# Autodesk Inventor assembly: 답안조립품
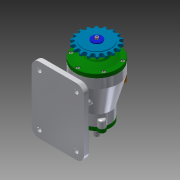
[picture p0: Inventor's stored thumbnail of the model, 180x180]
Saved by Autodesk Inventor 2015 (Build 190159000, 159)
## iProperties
Created: 2021-10
Part Number: 답안조립품
Document SubType Name: Assembly
Designer: 10259o
Author: 10259o
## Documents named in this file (16)
- C:\Users\10259o\Desktop\711006v1020\답안조립품.iam
- C:\Users\10259o\Desktop\711006v1020\본체.ipt
- C:\Users\10259o\Desktop\711006v1020\뒤커버.ipt
- C:\Users\10259o\Desktop\711006v1020\마개.ipt
- C:\Users\10259o\Desktop\711006v1020\베어링 6200.ipt
- C:\Users\10259o\Desktop\711006v1020\베어링 6203.ipt
- C:\Users\10259o\Desktop\711006v1020\볼트 M4.ipt
- 볼트 M4 x 12.ipt
- C:\Users\10259o\Desktop\711006v1020\스프로킷.ipt
- C:\Users\10259o\Desktop\711006v1020\앞커버.ipt
- C:\Users\10259o\Desktop\711006v1020\오일 실 10x20x7.ipt
- C:\Users\10259o\Desktop\711006v1020\오일 실 17x30x8.ipt
- C:\Users\10259o\Desktop\711006v1020\와셔.ipt
- C:\Users\10259o\Desktop\711006v1020\축.ipt
- C:\Users\10259o\Desktop\711006v1020\키 5x5.ipt
- 키 5 x 5.ipt
